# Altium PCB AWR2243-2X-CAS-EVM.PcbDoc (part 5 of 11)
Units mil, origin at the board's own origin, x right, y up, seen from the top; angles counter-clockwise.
Board outline 5118.11 x 3937.01 mil, 8 copper layers (Layer 1 - Top Layer, Layer 2 - GND, Layer 3 - Signal (Sensitive), Layer 4 - GND / Signal, Layer 5 - Signal, Layer 6 - PWR / Signal, Layer 7 - GND, Layer 8 - Bottom Layer), stack 54.8 mil thick; 629 components, 407 nets, 2243 pads, 3950 vias.
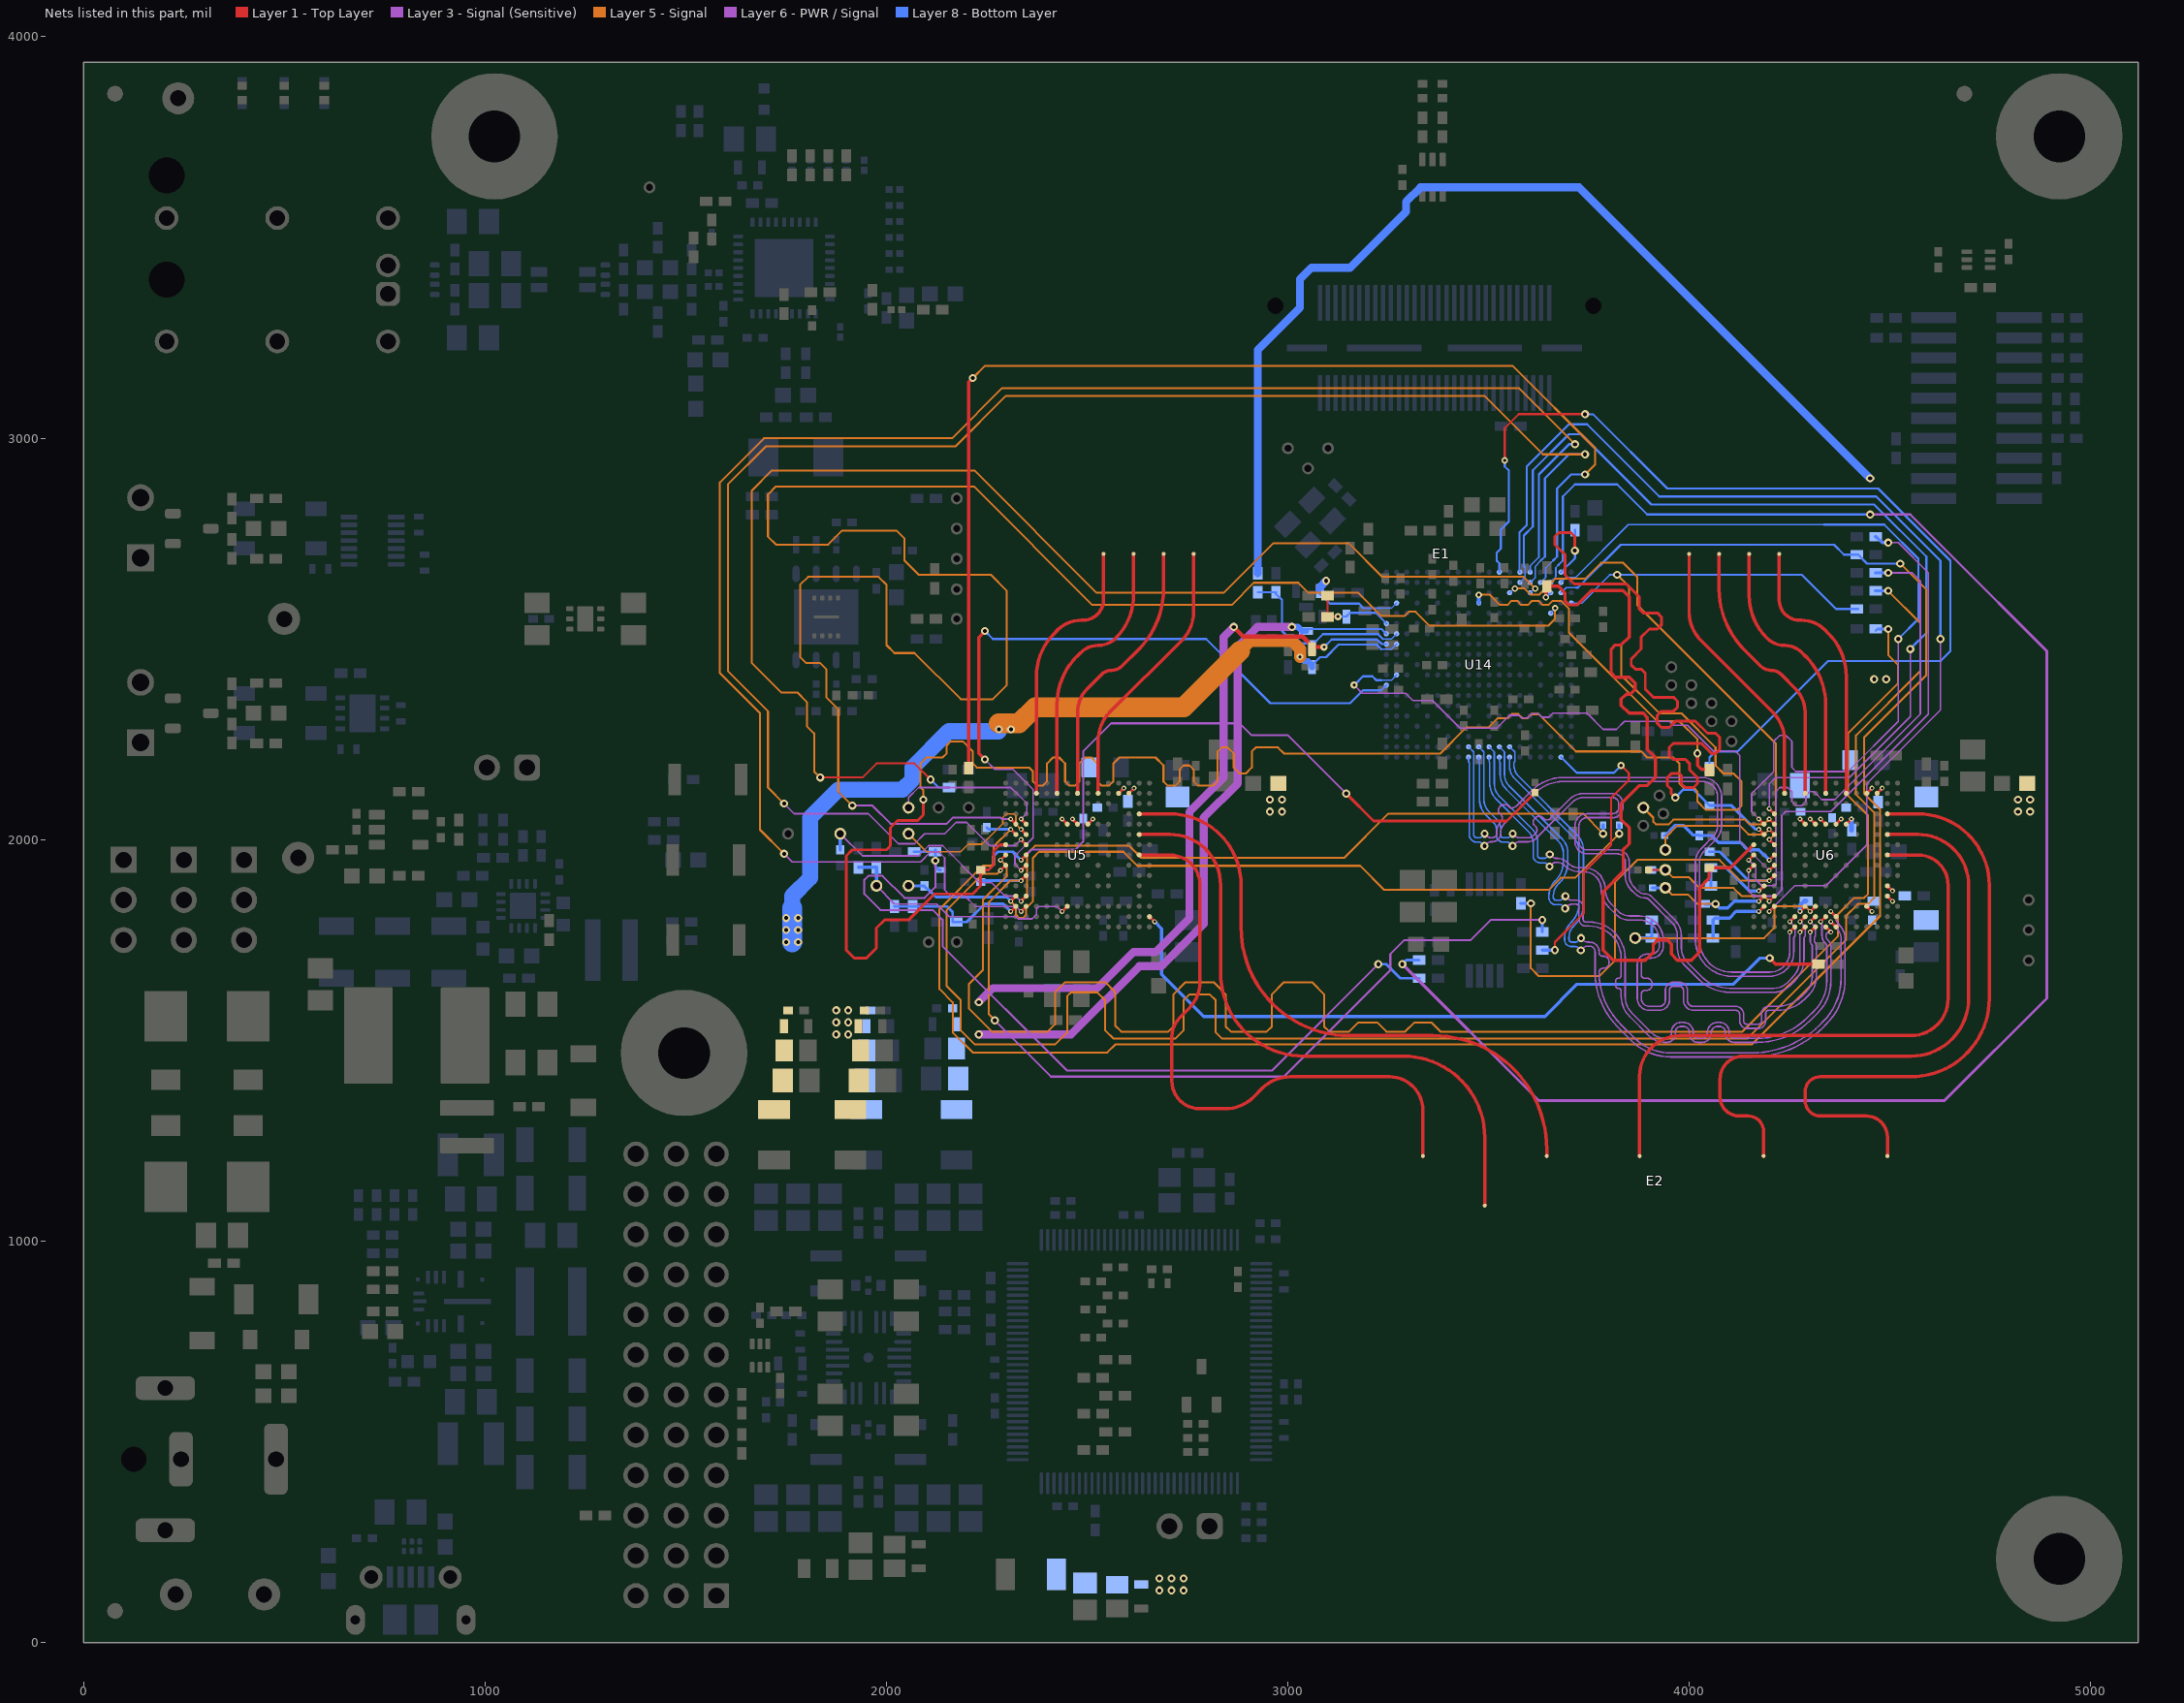
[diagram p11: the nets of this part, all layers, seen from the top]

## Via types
v1: diameter 13.78, hole 5.91, Layer 1 - Top Layer to Layer 2 - GND, tented top, 2104 vias
v2: diameter 20, hole 10, Layer 1 - Top Layer to Layer 8 - Bottom Layer, tented both sides, 831 vias
v3: diameter 7.87, hole 3.94, Layer 1 - Top Layer to Layer 2 - GND, tented top, 510 vias
v4: diameter 12, hole 6, Layer 1 - Top Layer to Layer 8 - Bottom Layer, tented both sides, 176 vias
v5: diameter 16, hole 8, Layer 1 - Top Layer to Layer 8 - Bottom Layer, tented both sides, 138 vias
v6: diameter 13.78, hole 5.91, Layer 1 - Top Layer to Layer 2 - GND, tented both sides, 88 vias
v7: diameter 18, hole 8, Layer 1 - Top Layer to Layer 8 - Bottom Layer, tented both sides, 41 vias
v8: diameter 22, hole 12, Layer 1 - Top Layer to Layer 8 - Bottom Layer, tented both sides, 36 vias
v9: diameter 19.68, hole 7.87, Layer 1 - Top Layer to Layer 8 - Bottom Layer, tented both sides, 26 vias

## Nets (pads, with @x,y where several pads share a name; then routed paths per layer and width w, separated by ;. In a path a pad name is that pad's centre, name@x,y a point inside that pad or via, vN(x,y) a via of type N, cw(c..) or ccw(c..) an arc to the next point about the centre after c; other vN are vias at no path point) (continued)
FE1_GPIO1: U5.N7 U14.V15 | length 4240.3
  Layer 1 - Top Layer w7: v4(2335.24,2000.39) U5.N7@2348.03,1987.6
  Layer 3 - Signal (Sensitive) w4: v2(1745,2090) 1770,2065 1955,2065 2030,1990 2070,1990 2095,2015 2145,2015 2173,2043 2200,2043 2258,1985 2319.84,1985 v4(2335.24,2000.39)
  Layer 5 - Signal w5: v2(1745,2090) 1705,2130 1705,2320 1605,2420 1605,2885 1700,2980 2171.72,2980 2296.72,3105 3490,3105 3635,2960 v2(3740,2960)
  Layer 8 - Bottom Layer w4: U14.V15@3603.86,2640.38 3616.14,2652.67 3616.14,2680.25 3629.44,2694.95
  Layer 8 - Bottom Layer w5.5: 3629.44,2694.95 3640,2705.52 3640,2900 3700,2960 v2(3740,2960)
FE1_GPIO2: U5.N13 U14.W15 | length 4384.6
  Layer 1 - Top Layer w7: v4(2335.24,1821.26) U5.N13@2348.03,1834.06
  Layer 3 - Signal (Sensitive) w4: v2(1745,1965) 1765,1945 2085,1945 2110,1970 2130,1970 2145,1955 2145,1875 2160,1860 2195,1860 2220.94,1834.06 2322.44,1834.06 v4(2335.24,1821.26)
  Layer 5 - Signal w5: v2(1745,1965) 1685,2025 1685,2315 1585,2415 1585,2890 1695,3000 2163.43,3000 2288.43,3125 3575,3125 v2(3715,2985)
  Layer 8 - Bottom Layer w4: U14.W15@3603.35,2666.46 3603.35,2682.3 3625,2703.95
  Layer 8 - Bottom Layer w5.5: 3625,2703.95 3625,2910 3700,2985 3711.36,2985 v2@3713.18,2986.82
FE1_I2C_SCL: R158.2 U14.U15 | length 3381.8
  Layer 1 - Top Layer w5: v2(1835,2155) 1940,2155 1975,2190 2070,2190 v2(2110,2150)
  Layer 5 - Signal w5: v2(1835,2155) 1820,2170 1820,2265 1802,2283 1802,2343 1778,2367 1738,2367 1665,2440 1665,2870 1715,2920 2218.79,2920 2523.79,2615 2774.87,2615 2840,2615 2963,2738 3152,2738 3235,2655 3587.07,2655 v5(3616.14,2625.93)
  Layer 8 - Bottom Layer w4: U14.U15@3603.35,2615.28 v5(3616.14,2625.93)
  Layer 8 - Bottom Layer w5: v2(2110,2150) 2130,2130 R158.2@2156.38,2130
FE1_I2C_SDA: R40.2 U14.V16 | length 3033.9
  Layer 1 - Top Layer w8: R40.2@2205,2178.62 2205,3140 v2(2215,3150)
  Layer 5 - Signal w5: v2(2215,3150) 2245,3180 3560,3180 3765,2975 3765,2935 v2(3740,2910)
  Layer 8 - Bottom Layer w4: U14.V16@3628.94,2640.87 3641.73,2653.66 3641.73,2676.73 3659.82,2694.82
  Layer 8 - Bottom Layer w5.5: 3659.82,2694.82 3670,2705 3670,2875 3705,2910 v2(3740,2910)
FE1_MCU_CLK_OUT: U5.N9 U14.H1 | length 1821.2
  Layer 1 - Top Layer w7: v4(2335.24,1923.62) U5.N9@2348.03,1936.42
  Layer 1 - Top Layer w8: v2(2245,2200) 2230,2215 2230,2503.89 2245,2518.89 v2(2245,2520)
  Layer 3 - Signal (Sensitive) w4: v2(2245,2200) 2270,2175 2315,2175 2365,2125 2365,2005 2320,1960 2320,1938.86 v4(2335.24,1923.62)
  Layer 8 - Bottom Layer w5.5: v2(2245,2520) 2265,2500 2796.36,2500 2956.36,2340 3155,2340 3187,2372 3232.12,2372 U14.H1@3245.08,2384.96
FE1_nERROR_OUT: R47.2 R181.1 U5.N8 | length 1841.6
  Layer 1 - Top Layer w7: v4(2335.24,1949.21) U5.N8@2348.03,1962.01 ; v2(3145,2115) 3213,2047 3544.99,2047 3609.44,2111.45 3610.23,2111.45 3615,2116.22 R47.2@3615,2117.01
  Layer 3 - Signal (Sensitive) w5: v4(2335.24,1949.21) 2361.02,1975 2470,1975 2490,1995 2490,2220 2560,2290 2880,2290 2910,2260 3000,2260 v2(3145,2115)
  Layer 8 - Bottom Layer w7: R181.1@2234.68,1925 2255,1925 2267,1937 2267,1959 2278,1970 2314.45,1970 v4(2335.24,1949.21)
FE1_nRESET: R161.2 R179.2 TP32.1 U5.P12 | length 2096.1
  Layer 1 - Top Layer w7: v4(2309.65,1846.85) U5.P12@2322.44,1859.65
  Layer 5 - Signal w5: v4(2309.65,1846.85) 2322.44,1834.06 2322.44,1812.56 2330,1805 2340,1805 2348.03,1813.03 2348.03,1830 2365,1846.97 2365,1955 2380,1970 2590,1970 2625,1935 3180,1935 3240,1875 3650,1875 3680,1905 3715,1905 v2(3825,2015)
  Layer 8 - Bottom Layer w7: TP32.1@2055,1885.2 2094.88,1885.2 R179.2@2095,1885.31 2095,1883.35 2101.34,1877 2103.31,1877 2123.31,1857 2299.5,1857 v4(2309.65,1846.85)
  Layer 8 - Bottom Layer w8: v2(3825,2015) R161.2@3825,2037.01
FE1_nWARM_RESET: R162.2 R175.1 TP26.1 U5.N12 | length 2267.7
  Layer 1 - Top Layer w7: v4(2335.24,1846.85) U5.N12@2348.03,1859.65
  Layer 3 - Signal (Sensitive) w4: TP26.1@1885,2015 1940,1960 2080,1960 2105,1985 2140,1985 2232,1893 2262,1893 2295.35,1859.65 2322.44,1859.65 v4(2335.24,1846.85)
  Layer 5 - Signal w5: v4(2335.24,1846.85) 2350,1861.61 2350,1965 2370,1985 2605,1985 2635,1955 3140,1955 3250,2065 3735,2065 v2(3785,2015)
  Layer 8 - Bottom Layer w8: R175.1@1884.68,1975 R175.1@1885,1974.68 TP26.1@1885,2015 ; v2(3785,2015) R162.2@3785,2037.01
FE1_OSC_CLKOUT: C61.2 U5.A14 | length 1902
  Layer 1 - Top Layer w7: U5.A14@2655.12,1808.46 v4(2667.91,1795.67)
  Layer 1 - Top Layer w8.4: v2(4200,1705) 4215,1690 C61.2@4321.38,1690
  Layer 8 - Bottom Layer w8: v4(2667.91,1795.67) 2685,1778.58 2685,1665 2790,1560 3640,1560 3720,1640 4110,1640 4175,1705 v2(4200,1705)
FE1_RS232_RX: TP20.1 U5.N5 | length 409.6
  Layer 1 - Top Layer w7: v4(2335.24,2051.57) U5.N5@2348.03,2038.78
  Layer 3 - Signal (Sensitive) w4: TP20.1@2055,2080 2055,2105 2080,2130 2310,2130 2350,2090 2350,2066.34 v4(2335.24,2051.57)
FE1_RS232_TX: TP27.1 U5.N6 | length 393.8
  Layer 1 - Top Layer w7: v4(2335.24,2025.98) U5.N6@2348.03,2013.19
  Layer 5 - Signal w4: TP27.1@2055,2015 2100,1970 2185,1970 2203.86,1988.86 2238.86,1988.86 2290,2040 2290,2055 2299.05,2064.05 2299.05,2064.37 2318.74,2064.37 2322.44,2060.67 2322.44,2038.78 v4(2335.24,2025.98)
FE1_RX1: "E1.D1 - RX1" U5.M2 | length 686.3
  Layer 1 - Top Layer w8.4: U5.M2@2373.62,2115.55 2373.62,2407.24 cw(c2524.28,2407.24) 2417.75,2513.77 2426.24,2522.26 cw(c2485.98,2462.51) 2485.98,2547.01 2489.77,2547.01 ccw(c2489.77,2598.22) 2525.98,2562.01 ccw(c2490.82,2597.18) 2540.55,2597.18 2540.55,2712.01
FE1_RX2: "E1.D1 - RX2" U5.K2 | length 686.3
  Layer 1 - Top Layer w8.4: U5.K2@2424.8,2115.55 2424.8,2337.17 cw(c2592.97,2337.17) 2474.06,2456.08 2484.31,2466.33 cw(c2526.98,2423.65) 2526.98,2484.01 ccw(c2526.98,2546.78) 2571.34,2502.36 ; 2571.34,2502.36 ccw(c2465.08,2608.62) 2615.35,2608.62 2615.35,2712.01
FE1_RX3: "E1.D1 - RX3" U5.H2 | length 686.8
  Layer 1 - Top Layer w8.4: U5.H2@2475.98,2115.55 2475.98,2316.65 cw(c2561.34,2316.65) 2476,2318.45 cw(c2561.34,2316.65) 2500.98,2377.01 2535.38,2411.4 cw(c2560.98,2385.79) 2560.98,2422.01 ccw(c2560.98,2458.22) 2586.59,2432.61 2627.75,2473.78 ccw(c2477.1,2624.43) 2690.16,2624.43 2690.16,2712.01
FE1_RX4: "E1.D1 - RX4" U5.F2 | length 686.3
  Layer 1 - Top Layer w8.4: U5.F2@2527.17,2115.55 2527.17,2246.77 cw(c2627.17,2246.77) 2556.45,2317.48 2735.67,2496.7 ccw(c2664.96,2567.41) 2764.96,2567.41 2764.96,2712.01
FE1_SCALED: C126.1 R26.1 R28.2 U14.P1 | length 214.6
  Layer 1 - Top Layer w5.5: R26.1@3098.62,2608 R28.2@3098.62,2555 3099.59,2555.97 v7(3125,2555.97)
  Layer 8 - Bottom Layer w5.5: v7(3125,2555.97) C126.1@3145.69,2555.97 3154.72,2565 3218.58,2565 U14.P1@3245.08,2538.5
FE1_SOP0: R171.2 R172.1 TP31.1 U5.J13 | length 632.3
  Layer 1 - Top Layer w7: v4(2437.6,1821.26) U5.J13@2450.39,1834.06
  Layer 3 - Signal (Sensitive) w4: TP31.1@1975,1885.2 2020.2,1840 2125,1840 2156.54,1808.46 2322.44,1808.46 2327.9,1803 2363,1803 2373.62,1813.62 2373.62,1827.62 2380.06,1834.06 2424.8,1834.06 v4(2437.6,1821.26)
  Layer 8 - Bottom Layer w8: R172.1@1930,1931.38 R171.2@1975,1931.38 TP31.1@1975,1885.2
FE1_SOP1_SYNC_OUT: R173.1 R174.2 R183.1 R203.2 | length 2153.5
  Layer 3 - Signal (Sensitive) w5: v2(2121.69,1948) 2121.69,1881.69 2095,1855 2045,1855 1990,1910 1955,1910 1945,1900 1945,1865 1985,1825 2115,1825 2140,1800 2140,1735 2450,1425 2960,1425 v2(3225,1690)
  Layer 8 - Bottom Layer w7: R174.2@2068.62,1970 R173.1@2121.38,1970 R173.1@2121.69,1970 ; R173.1@2121.69,1975 R173.1@2121.69,1970 ; R183.1@2135,1925 2130,1925 2121.69,1933.31 v2(2121.69,1948) R173.1@2121.69,1970 ; v2(3225,1690) 3245,1690 3280,1655 R203.2@3326.38,1655
FE1_SOP2: R188.2 R189.1 R193.1 U5.P13 | length 364.8
  Layer 1 - Top Layer w7: v4(2309.65,1821.26) U5.P13@2322.44,1834.06
  Layer 8 - Bottom Layer w7: R189.1@2020,1833.62 R188.2@2065,1833.62 2151.38,1833.62 2165,1820 2165,1795 R193.1@2173.62,1795 2200,1795 2245,1840 2290.9,1840 v4(2309.65,1821.26)
FE1_SPI_CLK: R140.1 U5.R9 | length 4271.6
  Layer 1 - Top Layer w7: v4(2284.05,1923.62) U5.R9@2296.85,1936.42
  Layer 5 - Signal w5: v4(2284.05,1923.62) 2275.43,1915 2240,1915 2150,1825 2150,1635 2185,1600 2185,1525 2220,1490 2420,1490 2450,1520 2450,1610 2460,1620 2525,1620 2545,1600 2545,1525 2565,1505 2720,1505 2740,1525 2740,1600 2755,1615 2805,1615 2820,1600 2820,1520 2835,1505 3110,1505 4043.05,1505 4145,1505 4390,1750 4390,1810 4420,1840 4445,1840 4460,1855 4460,2068 4415,2113 4415,2260 4575,2420 4575,2540 v2(4495,2620)
  Layer 8 - Bottom Layer w8: R140.1@4463.62,2620 v2(4495,2620)
FE1_SPI_CS0: R56.1 R141.1 U5.R7 U14.T19 | length 5713.8
  Layer 1 - Top Layer w7: v2(2092,2100) 2092,2062 2078,2048 2028,2048 2010,2030 2010,1985 2000,1975 1915,1975 1900,1960 1900,1725 1920,1705 1950,1705 1975,1730 1975,1780 1995,1800 2055,1800 2120,1865 2215,1865 2234.68,1884.68 R56.1@2234.68,1925 2255,1925 2267,1937 2267,1972 2282.6,1987.6 U5.R7@2296.85,1987.6
  Layer 5 - Signal w5: v2(2092,2100) 2092,2123 2085,2130 2085,2190 2100,2205 2140,2205 2150,2215 2150,2235 2160,2245 2190,2245 2215,2220 2215,2190 2225,2180 2355,2180 2365,2170 2365,2145 2375,2135 2390,2135 2400,2145 2400,2190 2415,2205 2430,2205 2445,2190 2445,2145 2455,2135 2470,2135 2480,2145 2480,2190 2495,2205 2510,2205 2525,2190 2525,2145 2535,2135 2555,2135 2565,2145 2565,2190 2580,2205 2670,2205 2690,2185 2690,2145 2700,2135 2720,2135 2730,2145 2730,2175 2740,2185 2755,2185 2765,2175 2765,2145 2775,2135 2815,2135 2825,2145 2825,2220 2835,2230 2850,2230 2865,2215 2865,2180 2880,2165 2895,2165 2910,2180 2910,2220 2920,2230 2975,2230 2990,2215 3380,2215 3445,2280 3500,2280 3523,2303 3548,2303 3558,2313 3574,2313 3584,2303 3597,2303 3607,2313 3624,2313 3717,2220 3880,2220 3895,2205 3960,2205 3975,2190 3975,2140 3985,2130 4010,2130 4020,2120 4020,2095 4040,2075 4120,2075 4130,2085 4130,2145 4110,2165 4085,2165 4065,2185 4065,2230 3980,2315 3925,2315 3830,2410 3830,2485 3850,2505 3850,2630 v2(3820,2660)
  Layer 8 - Bottom Layer w4: U14.T19@3705.71,2589.69 3731.69,2589.69 3802,2660
  Layer 8 - Bottom Layer w5.5: 3802,2660 v2(3820,2660) 4280,2660 4365,2575 R141.1@4416.38,2575 R141.1@4420.32,2575
FE1_SPI_IRQ: R136.2 R160.2 U5.P6 U14.U18 | length 5055.7
  Layer 1 - Top Layer w7: v4(2309.64,2025.98) U5.P6@2322.44,2013.19
  Layer 5 - Signal w5: v4(2309.64,2025.98) 2267,1983.34 2267,1942 2260,1935 2240,1935 2132,1827 2132,1628 2165,1595 2165,1520 2215,1470 2550,1470 2570,1490 4048.05,1490 4155,1490 4475,1810 4475,2075 4435,2115 4435,2255 4590,2410 4590,2623 v2(4525,2688)
  Layer 8 - Bottom Layer w4: U14.U18@3680.12,2615.28 3692.91,2628.07 3718.09,2628.07
  Layer 8 - Bottom Layer w5.5: 3718.09,2628.07 3722.07,2628.07 3829,2735 4360,2735 4385,2710 R136.2@4416.38,2710 4420.32,2710 4442.32,2688 v2(4525,2688)
  Layer 8 - Bottom Layer w7: R160.2@2250,2030.31 2254.33,2025.98 v4(2309.64,2025.98)
FE1_SPI_MISO: U5.P5 U14.R17 | length 5084.7
  Layer 1 - Top Layer w7: v4(2309.64,2051.57) U5.P5@2322.44,2038.78
  Layer 3 - Signal (Sensitive) w5: v2(1915,2085) 1965,2085 2010,2040 2150,2040 2165,2055 2285,2055 2288.43,2051.57 v4(2309.64,2051.57)
  Layer 5 - Signal w5: v2(1915,2085) 1880,2120 1880,2325 1850,2355 1850,2425 1835,2440 1800,2440 1785,2455 1785,2635 1805,2655 1980,2655 2000,2635 2000,2485 2020,2465 2070,2465 2185,2350 2265,2350 2300,2385 2300,2620 2260,2660 2080,2660 2045,2695 2045,2750 2025,2770 1890,2770 1855,2735 1725,2735 1705,2755 1705,2860 1725,2880 2217.57,2880 2512.57,2585 2860,2585 2915,2640 3025.64,2640 3050.64,2615 3175,2615 3232.8,2557.2 3290.2,2557.2 3301,2568 3318,2568 3353,2533 3648,2533 3665.18,2550.18 v5(3665.18,2576.89)
  Layer 8 - Bottom Layer w4: U14.R17@3654.53,2564.09 v5(3665.18,2576.89)
FE1_SPI_MOSI: R145.1 U5.R8 | length 4274.9
  Layer 1 - Top Layer w7: v4(2284.05,1949.21) U5.R8@2296.85,1962.01
  Layer 5 - Signal w5: v4(2284.05,1949.21) 2300,1933.27 2300,1910 2240,1850 2240,1675 2205,1640 2205,1580 2263.05,1521.95 2401.95,1521.95 2420,1540 2420,1620 2445,1645 2545,1645 2570,1620 2570,1536.95 2585,1521.95 2701.95,1521.95 2715,1535 2715,1615 2745,1645 2815,1645 2845,1615 2845,1535 2858.05,1521.95 2946.95,1521.95 2960,1535 2960,1615 2990,1645 3060,1645 3090,1615 3090,1535 3103.05,1521.95 3151.95,1521.95 3175,1545 3221.95,1545 3245,1521.95 3291.95,1521.95 3315,1545 3356.95,1545 3380,1521.95 3920,1521.95 4131.95,1521.95 4370,1760 4370,1815 4410,1855 4435,1855 4445,1865 4445,2060 4395,2110 4395,2265 4520,2390 4520,2435 4495,2460 v2(4495,2525)
  Layer 8 - Bottom Layer w5: R145.1@4463.62,2520 R145.1@4468.62,2525
  Layer 8 - Bottom Layer w8: R145.1@4468.62,2525 v2(4495,2525)
FE1_SYNC_FROM_SOC: R201.2 U14.V17 | length 4378.1
  Layer 3 - Signal (Sensitive) w5.5: v2(4450,2810) 4550,2810 4770,2590
  Layer 3 - Signal (Sensitive) w7: v2(3285,1690) 3625,1350 4635,1350 4890,1605 4890,2470 4770,2590
  Layer 8 - Bottom Layer w4: U14.V17@3654.53,2640.87 3654.53,2642.57 3667.32,2655.37 3667.32,2677.91 3673.93,2684.52
  Layer 8 - Bottom Layer w5.5: 3673.93,2684.52 3685,2695.59 3685,2855 3715,2885 3820,2885 3895,2810 v2(4450,2810)
  Layer 8 - Bottom Layer w7: v2(3285,1690) 3295,1700 R201.2@3326.38,1700
FE1_SYNC_IN: R185.2 R195.1 U5.N10 | length 2164.9
  Layer 1 - Top Layer w7: v4(2335.24,1898.03) U5.N10@2348.03,1910.83
  Layer 3 - Signal (Sensitive) w5: v2(2270,1550) 2410,1410 2990,1410 3255,1675 3255,1715 3290,1750 3455,1750 3505,1800 v2(3633.62,1800)
  Layer 5 - Signal w5: v2(2270,1550) 2255,1565 2255,1845 2308.03,1898.03 v4(2335.24,1898.03)
  Layer 8 - Bottom Layer w7: R185.2@2234.69,1890 R185.2@2234.68,1895 2237.72,1898.03 v4(2335.24,1898.03) ; R195.1@3633.62,1770 v2(3633.62,1800)
FE1_TX1: "E2.D1 - TX1" U5.B4 | length 1554.4
  Layer 1 - Top Layer w8.4: U5.B4@2629.53,2064.37 2705.98,2064.37 cw(c2705.98,1887.01) 2883.35,1887.01 2883.35,1781.12 ccw(c3152.46,1781.12) 3152.46,1512.01 3361.81,1512.01 cw(c3361.81,1229.26) 3644.57,1229.26 3644.57,1212.01
FE1_TX2: "E2.D1 - TX2" U5.B6 | length 1554.8
  Layer 1 - Top Layer w8.4: U5.B6@2629.53,2013.19 2705.98,2013.19 cw(c2705.98,1887.01) 2832.17,1887.01 2832.17,1669.11 ccw(c3040.44,1669.11) 3040.44,1460.83 3287.42,1460.83 cw(c3287.42,1257.93) 3490.31,1257.93 3490.32,1088.58
FE1_TX3: "E2.D1 - TX3" U5.B8 | length 1554.8
  Layer 1 - Top Layer w8.4: U5.B8@2629.53,1962.01 2705.98,1962.01 cw(c2705.98,1887.01) 2780.98,1887.01 2780.98,1647.01 cw(c2684.42,1647.01) 2752.7,1578.72 2730.98,1557.01 ccw(c2779.27,1508.72) 2710.98,1508.72 2710.98,1399.02 ccw(c2780,1399.02) 2780,1330 2843.58,1330 ccw(c2843.58,1430) 2914.29,1359.29 2935.36,1380.36 cw(c3006.07,1309.65) 3006.07,1409.65 3252.58,1409.65 cw(c3252.58,1326.2) 3336.02,1326.2 3336.02,1212.01
FE1_VRF1_FILTERED: C64.1 C67.1 C69.1 C73.1 C128.1 C132.1 C141.1 C147.1 L5.2 U5.G5 U5.H5 U5.J5 U14.M2 | length 2112.9
  Layer 1 - Top Layer w7: v4(2437.6,2051.57) U5.J5@2450.39,2038.78 ; v4(2463.19,2051.57) U5.H5@2475.98,2038.78 ; U5.G5@2501.57,2038.78 v4(2514.37,2051.58)
  Layer 5 - Signal w30: 2880,2470 2905,2495 3010,2495 3030,2475 v5(3030,2455)
  Layer 5 - Signal w50: 2280,2290 2330,2290 2370,2330 2740,2330 2880,2470
  Layer 8 - Bottom Layer w4: 3232.37,2474.53 3257.87,2474.53 U14.M2@3270.67,2487.32
  Layer 8 - Bottom Layer w5.5: C128.1@3060,2435 3080,2455 3095,2455 3126,2486 3220.89,2486 3232.37,2474.53
  Layer 8 - Bottom Layer w15: v5(3030,2455) 3040,2445 3050,2445 C128.1@3060,2435 ; C128.1@3060,2435 C128.1@3060,2430 C128.1@3060,2435
  Layer 8 - Bottom Layer w40: 1765,1830 1765,1860 1810,1905 1810,2055 1880,2125 2040,2125 2065,2150 2065,2180 2155,2270 v2@2280,2270
  Layer 8 - Bottom Layer w50: 1765,1745 1765,1830
  other v2: 1750,1745 1780,1745 1750,1775 1780,1775 1750,1805 1780,1805 2280,2275 2310,2275
FE1_VRF2_FILTERED: C65.1 C68.1 C70.1 C74.1 C123.1 C134.1 C138.1 L6.2 R44.2 U5.C2 U5.D2 U14.T2 | length 285.6
  Layer 1 - Top Layer w7: U5.D2@2578.35,2115.55 v4(2591.14,2128.35) ; U5.C2@2603.94,2115.55 v4(2616.73,2128.35)
  Layer 8 - Bottom Layer w4: 3228.29,2576.89 3257.87,2576.89 U14.T2@3270.67,2589.69
  Layer 8 - Bottom Layer w5.5: C123.1@3080,2620 3080,2612.5 3104.5,2588 3177,2588 3188.11,2576.89 3228.29,2576.89
  Layer 8 - Bottom Layer w20: C123.1@3080,2620 3080,2630 v2(3095,2645)
  other v2: 1875,1515 1905,1515 1875,1545 1905,1545 1875,1575 1905,1575 2955,2070 2985,2070 2955,2100 2985,2100
FE2_1V8_FILTERED: C135.1 C142.1 C148.1 C160.1 C163.1 C166.1 C168.1 C171.1 C239.1 C240.1 C241.1 L23.2 R138.2 U6.B11 U6.B12 U6.D13 U6.F5 U6.K5 U6.K13 | length 2776.7
  Layer 1 - Top Layer w7: v4(4275.39,1821.26) U6.K13@4288.19,1834.06 ; v4(4275.39,2051.57) U6.K5@4288.19,2038.78 ; U6.F5@4390.55,2038.78 v4(4403.35,2051.58) ; U6.D13@4441.73,1834.06 v4(4454.53,1821.26) ; U6.B12@4492.91,1859.65 v4(4505.71,1846.85) ; U6.B11@4492.91,1885.24 v4(4505.71,1872.44)
  Layer 8 - Bottom Layer w12: v4(4275.39,1821.26) 4275.39,1835.59 4286.81,1847.01 C163.1@4290.75,1847.01 ; C148.1@4403.35,2023.66 v4(4403.35,2051.58)
  Layer 8 - Bottom Layer w20: R138.2@2925,2663.62 2925,3220 3030,3325 3030,3396.25 3058.75,3425 3155,3425 3294.08,3564.08 3294.08,3589.08 3330,3625 3725,3625 v2(4450,2900)
  other v2: 2680,130 2710,130 2740,130 2680,160 2710,160 2740,160 4460,2400 4490,2400
FE2_CSI2_CLK_N: U6.J14 U14.A11 | length 1726.1
  Layer 1 - Top Layer w7: v4(4300.98,1795.67) U6.J14@4313.78,1808.46
  Layer 3 - Signal (Sensitive) w4: v2(3651.5,1933.16) 3657.76,1939.42 cw(c3668,1929.18) 3668,1943.66 3671,1943.66 cw(c3671,1918.7) 3688.64,1936.36 3690,1935 ccw(c3726.21,1971.21) 3726.21,1920 3737.68,1920 cw(c3737.68,1877.68) 3780,1877.68 ccw(c3844.75,1877.68) 3798.97,1831.89 3817.32,1813.54 ccw(c3850,1846.21) 3850,1800 3875,1800 cw(c3875,1750) 3925,1750 3925,1735.49 cw(c3904.51,1735.49) 3904.51,1715 3895,1715 ccw(c3895,1690) 3870,1690 3870,1605 ccw(c3900,1605) 3900,1575 3925,1575 ccw(c3925,1600) 3950,1600 3950,1625 cw(c3960,1625) 3960,1635 3975,1635 cw(c3975,1625) 3985,1625 3985,1600 ccw(c4010,1600) 4010,1575 4115,1575 cw(c4115,1565) 4125,1565 4125,1549.14 ccw(c4144.14,1549.14) 4144.14,1530 4170.86,1530 ccw(c4170.86,1549.14) 4190,1549.14 4190,1567.93 cw(c4197.07,1567.93) 4197.07,1575 4219.64,1575 ccw(c4219.64,1670.36) 4287.07,1602.93 4297.07,1612.93 ccw(c4251.37,1658.63) 4316,1658.63 4316,1735.34 ccw(c4302.34,1735.34) 4312,1745 cw(c4314.45,1747.45) 4310.98,1747.45 4310.98,1754.58 cw(c4315.82,1754.58) 4312.4,1758 ccw(c4309.07,1761.33) 4313.78,1761.33 4313.78,1777 ccw(c4299.6,1777) 4309.63,1787.03 v4(4300.98,1795.67)
  Layer 8 - Bottom Layer w4: U14.A11@3500.98,2205.83 3500.98,2193.85 3502.78,2192.06 3502.78,2140 ccw(c3559.12,2140) 3519.28,2100.16 3599.72,2019.72 cw(c3572.49,1992.49) 3611,1992.49 3611,1959.66 ccw(c3628,1959.66) 3628,1942.66 3638,1942.66 cw(c3638,1933.01) 3644.82,1939.84 v2(3651.5,1933.16)
FE2_CSI2_CLK_P: U6.J15 U14.B11 | length 1726.1
  Layer 1 - Top Layer w7: v4(4300.98,1770.08) U6.J15@4313.78,1782.87
  Layer 3 - Signal (Sensitive) w4: v2(3652,1963.66) 3657.77,1957.9 ccw(c3668,1968.15) 3668,1953.66 3671,1953.66 cw(c3671,1918.7) 3695.72,1943.42 3697.07,1942.07 ccw(c3726.21,1971.21) 3726.21,1930 3737.68,1930 cw(c3737.68,1877.68) 3790,1877.68 ccw(c3844.75,1877.68) 3806.03,1838.97 3824.39,1820.61 ccw(c3850,1846.21) 3850,1810 3875,1810 cw(c3875,1750) 3935,1750 3935,1735.48 cw(c3904.52,1735.48) 3904.52,1705 3895,1705 ccw(c3895,1690) 3880,1690 3880,1663.46 ccw(c3888.46,1663.46) 3888.46,1655 3893.34,1655 cw(c3893.34,1641.34) 3907,1641.34 3907,1638.66 cw(c3893.34,1638.66) 3893.34,1625 3890.24,1625 ccw(c3890.24,1614.76) 3880,1614.76 3880,1605 ccw(c3900,1605) 3900,1585 3925,1585 ccw(c3925,1600) 3940,1600 3940,1625 cw(c3960,1625) 3960,1645 3975,1645 cw(c3975,1625) 3995,1625 3995,1600 ccw(c4010,1600) 4010,1585 4115,1585 cw(c4115,1565) 4135,1565 4135,1549.14 ccw(c4144.14,1549.14) 4144.14,1540 4170.86,1540 ccw(c4170.86,1549.14) 4180,1549.14 4180,1567.93 cw(c4197.07,1567.93) 4197.07,1585 4219.64,1585 ccw(c4219.64,1670.36) 4280,1610 4290,1620 ccw(c4251.37,1658.63) 4306,1658.63 4306,1735.34 ccw(c4302.34,1735.34) 4304.93,1737.93 cw(c4314.45,1747.45) 4300.98,1747.45 v4(4300.98,1770.08)
  Layer 8 - Bottom Layer w4: U14.B11@3500.98,2231.42 3513.78,2218.62 3513.78,2140 ccw(c3559.12,2140) 3527.06,2107.94 3607.5,2027.5 cw(c3572.49,1992.49) 3622,1992.49 3622,1960.49 ccw(c3628.83,1960.49) 3628.83,1953.66 3638,1953.66 ccw(c3638,1963.32) 3644.82,1956.49 v2(3652,1963.66)
FE2_CSI2_TX0_N: U6.G14 U14.A13 | length 1725.8
  Layer 1 - Top Layer w7: v4(4352.17,1821.26) U6.G14@4364.96,1808.46
  Layer 3 - Signal (Sensitive) w4: v2(3729.5,1724.5) 3735.76,1730.76 cw(c3746,1720.52) 3746,1735 3751.34,1735 cw(c3751.34,1721.34) 3765,1721.34 3765,1669.76 ccw(c3957.55,1669.76) 3821.4,1533.6 3855.6,1499.4 ccw(c3953.14,1596.94) 3953.14,1459 4155.02,1459 ccw(c4155.02,1710.38) 4332.77,1532.63 4340.45,1540.3 ccw(c4226.23,1654.52) 4387.76,1654.52 4387.76,1749.81 ccw(c4328.82,1749.81) 4370.49,1791.48 4368.9,1793.08 cw(c4378.42,1802.59) 4364.96,1802.59 ccw(c4350.78,1802.59) 4360.81,1812.62 v4(4352.17,1821.26)
  Layer 8 - Bottom Layer w4: U14.A13@3552.17,2205.83 3552.17,2182.23 ccw(c3594.48,2182.23) 3564.56,2152.31 3712.37,2004.5 cw(c3681.87,1974) 3725,1974 3725,1840.11 cw(c3660.89,1840.11) 3706.22,1794.78 3704.56,1793.11 ccw(c3742.11,1755.56) 3689,1755.56 3689,1751 ccw(c3706,1751) 3706,1734 3716,1734 cw(c3716,1724.34) 3722.83,1731.17 v2(3729.5,1724.5)
FE2_CSI2_TX0_P: U6.G15 U14.B13 | length 1726.1
  Layer 1 - Top Layer w7: v4(4352.17,1795.67) U6.G15@4364.96,1782.87
  Layer 3 - Signal (Sensitive) w4: v2(3730,1755) 3735.77,1749.23 ccw(c3746,1759.49) 3746,1745 3751.34,1745 cw(c3751.34,1721.34) 3775,1721.34 3775,1718.46 ccw(c3783.46,1718.46) 3783.46,1710 3786.34,1710 cw(c3786.34,1696.34) 3800,1696.34 3800,1693.48 cw(c3786.52,1693.48) 3786.52,1680 3785.24,1680 ccw(c3785.24,1669.76) 3775,1669.76 ccw(c3957.55,1669.76) 3828.47,1540.67 3862.67,1506.47 ccw(c3953.14,1596.94) 3953.14,1469 4155.02,1469 ccw(c4155.02,1710.38) 4325.7,1539.7 4333.38,1547.38 ccw(c4226.23,1654.52) 4377.76,1654.52 4377.76,1749.81 ccw(c4328.82,1749.81) 4363.42,1784.41 v4(4352.17,1795.67)
  Layer 8 - Bottom Layer w4: U14.B13@3552.17,2231.42 3564.96,2218.62 3564.96,2194.74 3563.17,2192.94 3563.17,2183.84 ccw(c3598.38,2183.84) 3573.48,2158.94 3720.15,2012.28 cw(c3681.87,1974) 3736,1974 3736,1840.11 cw(c3660.89,1840.11) 3714,1787 3712.33,1785.34 ccw(c3742.11,1755.56) 3700,1755.56 3700,1751.83 ccw(c3706.83,1751.83) 3706.83,1745 3716,1745 ccw(c3716,1754.66) 3722.83,1747.82 v2(3730,1755)
FE2_CSI2_TX1_N: U6.H14 U14.B12 | length 1725.8
  Layer 1 - Top Layer w7: v4(4326.57,1795.67) U6.H14@4339.37,1808.46
  Layer 3 - Signal (Sensitive) w4: v2(3691,1859.33) 3696.77,1853.57 ccw(c3707,1863.82) 3707,1849.33 3717.84,1849.33 cw(c3717.84,1832.17) 3735,1832.17 3735,1802.07 ccw(c3742.07,1802.07) 3742.07,1795 3750,1795 cw(c3750,1705) 3840,1705 3840,1610 ccw(c3900.36,1610) 3857.68,1567.32 3905.86,1519.14 ccw(c3940,1553.28) 3940,1505 3943.1,1505 ccw(c3943.1,1516.9) 3955,1516.9 3955,1521.1 cw(c3978.9,1521.1) 3978.9,1545 3984.68,1545 cw(c3984.68,1519.68) 4010,1519.68 4010,1516.9 ccw(c4021.9,1516.9) 4021.9,1505 4030.24,1505 ccw(c4030.24,1518.9) 4044.14,1518.9 cw(c4070.24,1518.9) 4070.24,1545 4075.24,1545 cw(c4075.24,1521.1) 4099.14,1521.1 4099.14,1518.41 ccw(c4112.56,1518.41) 4112.56,1505 4168.49,1505 ccw(c4168.49,1682.46) 4293.98,1556.98 4311.5,1574.5 ccw(c4237.45,1648.54) 4342.17,1648.54 4342.17,1734 ccw(c4330.49,1734) 4338.76,1742.24 4337,1744 cw(c4353.9,1760.9) 4330,1760.9 4330,1787.4 ccw(c4318.31,1787.4) v4@4326.73,1795.51 ; v4@4326.73,1795.51 ccw(c4318.31,1787.4) v4(4326.57,1795.67) v4@4326.73,1795.51
  Layer 8 - Bottom Layer w4: U14.B12@3526.57,2231.42 3539.37,2218.62 3539.37,2163.36 ccw(c3582.18,2163.36) 3551.91,2133.09 3682.17,2002.83 cw(c3646.3,1967) 3697,1967 3697,1944.44 cw(c3621.89,1944.44) 3675,1891.33 3673.33,1889.67 ccw(c3703.11,1859.89) 3661,1859.89 3661,1856.16 ccw(c3667.83,1856.16) 3667.83,1849.33 3677,1849.33 ccw(c3677,1858.99) 3683.82,1852.16 v2(3691,1859.33)
FE2_CSI2_TX1_P: U6.H15 U14.A12 | length 1726.5
  Layer 1 - Top Layer w7: U6.H15@4339.37,1782.87 v4(4352.17,1770.08)
  Layer 3 - Signal (Sensitive) w4: v2(3690.5,1828.83) 3696.76,1835.09 cw(c3707,1824.85) 3707,1839.33 3717.84,1839.33 cw(c3717.84,1832.17) 3725,1832.17 3725,1802.07 ccw(c3742.07,1802.07) 3742.07,1785 3750,1785 cw(c3750,1705) 3830,1705 3830,1662 cw(c3823,1662) 3823,1655 ccw(c3823,1648) 3816,1648 3816,1637 ccw(c3823,1637) 3823,1630 cw(c3823,1623) 3830,1623 3830,1610 ccw(c3900.36,1610) 3850.61,1560.25 3898.79,1512.07 ccw(c3940,1553.28) 3940,1495 3943.1,1495 ccw(c3943.1,1516.9) 3965,1516.9 3965,1521.1 cw(c3978.9,1521.1) 3978.9,1535 3984.68,1535 cw(c3984.68,1519.68) 4000,1519.68 4000,1516.9 ccw(c4021.9,1516.9) 4021.9,1495 4027.5,1495 4030.24,1495 ccw(c4030.24,1518.9) 4054.14,1518.9 cw(c4070.24,1518.9) 4070.24,1535 4075.24,1535 cw(c4075.24,1521.1) 4089.14,1521.1 4089.14,1518.41 ccw(c4112.56,1518.41) 4112.56,1495 4168.49,1495 ccw(c4168.49,1682.46) 4301.05,1549.91 4318.57,1567.43 ccw(c4237.45,1648.54) 4352.17,1648.54 4352.17,1734 ccw(c4330.49,1734) 4345.82,1749.32 4344.07,1751.07 cw(c4353.9,1760.9) 4340,1760.9 cw(c4349.18,1760.9) 4349.18,1770.08 v4(4352.17,1770.08)
  Layer 8 - Bottom Layer w4: U14.A12@3526.57,2205.83 3526.57,2193.85 3528.37,2192.06 3528.37,2163.36 ccw(c3582.18,2163.36) 3544.13,2125.31 3674.37,1995.07 cw(c3646.3,1967) 3686,1967 3686,1944.44 cw(c3621.89,1944.44) 3667.22,1899.11 3665.56,1897.44 ccw(c3703.11,1859.89) 3650,1859.89 3650,1855.33 ccw(c3667,1855.33) 3667,1838.33 3677,1838.33 cw(c3677,1828.67) 3683.82,1835.51 v2(3690.5,1828.83)
FE2_CSI2_TX2_N: U6.K14 U14.A10 | length 1726.8
  Layer 1 - Top Layer w7: v4(4275.39,1795.67) U6.K14@4288.19,1808.46
  Layer 3 - Signal (Sensitive) w4: v2(3559.5,1984.5) 3565.76,1990.76 cw(c3576,1980.52) 3576,1995 3599.39,1995 ccw(c3599.39,2020.61) 3617.5,2002.5 3709.39,2094.39 cw(c3735,2068.79) 3735,2105 3808.68,2105 cw(c3808.68,2089.68) 3824,2089.68 3824,2080.32 cw(c3808.68,2080.32) 3808.68,2065 3745,2065 ccw(c3745,2035) 3715,2035 3715,1995 ccw(c3745,1995) 3745,1965 3820,1965 cw(c3820,1945) 3840,1945 3840,1911.21 ccw(c3891.21,1911.21) 3854.99,1875.01 3864.39,1865.61 ccw(c3890,1891.21) 3890,1855 cw(c3890,1842.93) 3898.54,1851.46 3955.86,1794.14 cw(c3921.72,1760) 3970,1760 3970,1729.75 ccw(c4029.75,1729.75) 3987.5,1687.5 4022.78,1652.22 ccw(c4100.56,1730) 4100.56,1620 4210,1620 ccw(c4210,1678.28) 4251.21,1637.07 4262.07,1647.93 ccw(c4205.76,1704.24) 4285.39,1704.24 4285.39,1754.58 cw(c4290.23,1754.58) 4286.81,1758 ccw(c4283.48,1761.33) 4288.19,1761.33 4288.19,1777 ccw(c4274.01,1777) 4284.04,1787.03 v4(4275.39,1795.67)
  Layer 8 - Bottom Layer w4: U14.A10@3475.39,2205.83 3475.39,2193.85 3477.19,2192.06 3477.19,2100 ccw(c3530.76,2100) 3492.88,2062.12 3512.5,2042.5 cw(c3496.81,2026.81) 3519,2026.81 3519,2011 ccw(c3536,2011) 3536,1994 3546,1994 cw(c3546,1984.34) 3552.82,1991.17 v2(3559.5,1984.5)
FE2_CSI2_TX2_P: U6.K15 U14.B10 | length 1726.5
  Layer 1 - Top Layer w7: v4(4275.39,1770.08) U6.K15@4288.19,1782.87
  Layer 3 - Signal (Sensitive) w4: v2(3560,2015) 3565.77,2009.23 ccw(c3576,2019.49) 3576,2005 3599.39,2005 ccw(c3599.39,2020.61) 3610.43,2009.57 3617.43,2016.57 ccw(c3611.22,2022.78) 3620,2022.78 3620,2027.17 ccw(c3613.17,2027.17) 3618.01,2031.99 3613.12,2036.88 cw(c3618.24,2042) 3611,2042 3611,2044.76 cw(c3621.24,2044.76) 3614,2052 3618,2056 cw(c3622.83,2051.17) 3622.83,2058 3627.76,2058 cw(c3627.76,2047.76) 3635,2055 3637.17,2052.83 ccw(c3644,2059.66) 3644,2050 3647.22,2050 ccw(c3647.22,2058.78) 3653.43,2052.57 3702.32,2101.46 cw(c3735,2068.79) 3735,2115 3808.68,2115 cw(c3808.68,2089.68) 3834,2089.68 3834,2080.32 cw(c3808.68,2080.32) 3808.68,2055 3745,2055 ccw(c3745,2035) 3725,2035 3725,1995 ccw(c3745,1995) 3745,1975 3820,1975 cw(c3820,1945) 3850,1945 3850,1911.21 ccw(c3891.21,1911.21) 3862.07,1882.07 3871.46,1872.68 ccw(c3890,1891.21) 3890,1865 cw(c3890,1842.93) 3905.61,1858.54 3962.93,1801.21 cw(c3921.72,1760) 3980,1760 3980,1729.75 ccw(c4029.75,1729.75) 3994.57,1694.57 4029.85,1659.29 ccw(c4100.56,1730) 4100.56,1630 4210,1630 ccw(c4210,1678.28) 4244.14,1644.14 4255,1655 ccw(c4205.76,1704.24) 4275.39,1704.24 v4(4275.39,1770.08)
  Layer 8 - Bottom Layer w4: U14.B10@3475.39,2231.42 3488.19,2218.62 3488.19,2100 ccw(c3530.76,2100) 3500.66,2069.9 3520.28,2050.27 cw(c3496.81,2026.81) 3530,2026.81 3530,2011.83 ccw(c3536.83,2011.83) 3536.83,2005 3546,2005 ccw(c3546,2014.66) 3552.82,2007.83 v2(3560,2015)
FE2_CSI2_TX3_N: U6.L14 U14.A9 | length 1726
  Layer 1 - Top Layer w7: v4(4249.8,1795.67) U6.L14@4262.6,1808.46
  Layer 3 - Signal (Sensitive) w4: v2(3489.5,1984.5) 3495.76,1990.76 cw(c3506,1980.52) 3506,1995 3509,1995 ccw(c3509,2016) 3530,2016 3530,2018.27 cw(c3560.73,2018.27) 3539,2040 3614.71,2115.71 cw(c3685.42,2045) 3685.42,2145 4032.2,2145 cw(c4032.2,2107.2) 4070,2107.2 4070,2035 cw(c4031.72,2035) 4058.79,2007.93 4028.54,1977.68 ccw(c4061.21,1945) 4015,1945 4015,1750.47 ccw(c4105.47,1750.47) 4105.47,1660 4199.8,1660 ccw(c4199.8,1720) 4259.8,1720 4259.8,1754.58 cw(c4264.64,1754.58) 4261.22,1758 ccw(c4257.89,1761.33) 4262.6,1761.33 4262.6,1777 ccw(c4248.42,1777) 4258.45,1787.03 v4(4249.8,1795.67)
  Layer 8 - Bottom Layer w4: U14.A9@3449.8,2205.83 3449.8,2193.85 3451.6,2192.06 3451.6,2013 ccw(c3470.6,2013) 3470.6,1994 3476,1994 cw(c3476,1984.34) 3482.82,1991.17 v2(3489.5,1984.5)
FE2_CSI2_TX3_P: U6.L15 U14.B9 | length 1726.4
  Layer 1 - Top Layer w7: v4(4249.8,1770.08) U6.L15@4262.6,1782.87
  Layer 3 - Signal (Sensitive) w4: v2(3490,2015) 3495.77,2009.23 ccw(c3506,2019.49) 3506,2005 3509,2005 ccw(c3509,2016) 3520,2016 3520,2018.27 cw(c3560.73,2018.27) 3531.93,2047.07 ccw(c3526.93,2052.07) 3534,2052.07 3534,2054 ccw(c3521.96,2054) 3530.47,2062.51 3526.13,2066.86 cw(c3531.27,2072) 3524,2072 3524,2072.34 cw(c3537.66,2072.34) 3527.99,2081.99 3530.5,2084.5 cw(c3536.54,2078.46) 3536.54,2087 3543.15,2087 cw(c3543.15,2080.15) 3547.99,2085 ; 3547.99,2084.99 3551.86,2081.13 ccw(c3557,2086.27) 3557,2079 ccw(c3557,2095.56) 3568.71,2083.85 3607.64,2122.78 cw(c3685.42,2045) 3685.42,2155 4032.2,2155 cw(c4032.2,2107.2) 4080,2107.2 4080,2035 cw(c4031.72,2035) 4065.86,2000.86 4035.61,1970.61 ccw(c4061.21,1945) 4025,1945 4025,1750.47 ccw(c4105.47,1750.47) 4105.47,1670 4199.8,1670 ccw(c4199.8,1720) 4249.8,1720 v4(4249.8,1770.08)
  Layer 8 - Bottom Layer w4: U14.B9@3449.8,2231.42 3462.6,2218.62 3462.6,2013 ccw(c3470.6,2013) 3470.6,2005 3476,2005 ccw(c3476,2014.66) 3482.82,2007.83 v2(3490,2015)
FE2_GPIO0: U6.N4 U14.V14 | length 2353.9
  Layer 1 - Top Layer w7: v4(4198.62,2077.17) U6.N4@4211.42,2064.37
  Layer 3 - Signal (Sensitive) w4: v4(4198.62,2077.17) 4198.62,2138.62 4215,2155 4398,2155 4550,2307 v2(4550,2475)
  Layer 8 - Bottom Layer w4: U14.V14@3577.75,2640.87 3590.55,2653.66 3590.55,2678.25
  Layer 8 - Bottom Layer w5.5: 3590.55,2678.25 3587.86,2680.95 3587.61,2680.95 3587.61,2757.61 3610,2780 3610,2920 3700,3010 3730,3010 3905,2835 4460,2835 4590,2705 4590,2515 v2(4550,2475)
FE2_GPIO1: U6.N7 U14.U13 | length 1198.3
  Layer 1 - Top Layer w7: v4(4198.62,2000.39) U6.N7@4211.42,1987.6
  Layer 5 - Signal w5: v5(3564.96,2625.93) 3589.07,2625.93 3605,2610 3625,2610 3665,2650 3740,2650 3780,2690 3835,2690 3870,2655 3870,2585 4215,2240 4215,2016.77 v4(4198.62,2000.39)
  Layer 8 - Bottom Layer w4: U14.U13@3552.17,2615.28 v5(3564.96,2625.93)
FE2_GPIO2: U6.N13 U14.W14 | length 2599.7
  Layer 1 - Top Layer w7: v4(4198.62,1821.26) U6.N13@4211.42,1834.06
  Layer 3 - Signal (Sensitive) w4: v4(4198.62,1821.26) 4262.6,1885.24 4340.24,1885.24 4441.73,1986.73 4441.73,2139.73 4625,2323 v2(4625,2500)
  Layer 8 - Bottom Layer w5: 3576.86,2765.79 3576.86,2667.36 U14.W14@3577.75,2666.46
  Layer 8 - Bottom Layer w5.5: 3576.86,2765.79 3595,2783.93 3595,2930 3700,3035 3745,3035 3925,2855 4465,2855 4625,2695 v2(4625,2500)
FE2_I2C_SCL: R156.2 U14.W12 | length 2619.7
  Layer 1 - Top Layer w5.5: v5(3540,2945) 3540,3025 3575,3060 v2(3740,3060)
  Layer 8 - Bottom Layer w5: v2(3740,3060) 3760,3060 3945,2875 4470,2875 4650,2695 4650,2470 4625,2445 4345,2445 4120,2220 4065,2220 4050,2205 R156.2@4050,2173.62
  Layer 8 - Bottom Layer w5.5: U14.W12@3526.57,2666.46 3526.57,2688.43 3520,2695 3520,2715 3530,2725 3530,2772.5 3550,2792.5 3550,2920 3540,2930 v5(3540,2945)
FE2_I2C_SDA: R41.2 U14.T10 | length 873.8
  Layer 1 - Top Layer w8: v2(4020,2215) 4020,2185 4030,2175 4048.62,2175 R41.2@4050,2173.62
  Layer 5 - Signal w5: v5(3475.39,2610) 3503,2610 3528,2585 3547,2585 3557,2595 3571,2595 3581,2585 3598,2585 3608,2595 3624,2595 3634,2585 3649,2585 3659,2595 3680,2595 3700,2575 3700,2515 3920,2295 3975,2295 4020,2250 v2(4020,2215)
  Layer 8 - Bottom Layer w10: U14.T10@3475.39,2589.69 v5(3475.39,2610)
FE2_MCU_CLK_OUT: U6.N9 U14.J2 | length 1551.8
  Layer 1 - Top Layer w7: v4(4198.62,1923.62) U6.N9@4211.42,1936.42
  Layer 3 - Signal (Sensitive) w4: v7(3165,2385) 3185,2365 3293,2365 3311,2347 3360,2347 3429,2278 3520,2278 3552,2310 3575,2310 3582,2303 3596,2303 3607,2314 3624,2314 3633,2305 3650,2305 3660,2315 3745,2315 3785,2275 3818,2275 3838,2295 3950,2295 3960,2285 3995,2285 4060,2220 4115,2220 4125,2210 4125,1997.24 v4(4198.62,1923.62)
  Layer 8 - Bottom Layer w4: 3232.84,2397.76 3257.87,2397.76 U14.J2@3270.67,2410.55
  Layer 8 - Bottom Layer w5.5: v7(3165,2385) 3187,2407 3210.27,2407 3219.51,2397.76 3232.84,2397.76
FE2_nERROR_OUT: R164.1 R168.2 U6.N8 | length 324.2
  Layer 1 - Top Layer w7: v4(4198.62,1949.21) U6.N8@4211.42,1962.01
  Layer 8 - Bottom Layer w8: R168.2@3938.23,2010.31 3939.01,2010.31 3963.7,2035 3985,2035 4008.16,2011.84 4023.47,2011.84 R164.1@4025,2010.32 4055,2010.32 4072.66,1992.66 4127.34,1992.66 4145,1975 4172.83,1975 v4(4198.62,1949.21)
FE2_nRESET: R187.2 R190.2 TP33.1 U6.P12 | length 341.1
  Layer 1 - Top Layer w7: v4(4173.03,1846.85) U6.P12@4185.83,1859.65
  Layer 5 - Signal w5: TP33.1@3940,1885 TP33.1@3940,1880 3957,1863 3997,1863 4020,1840 v2(4065,1840)
  Layer 8 - Bottom Layer w8: R187.2@3907.99,1880 TP33.1@3940,1880 ; R190.2@4039.68,1840 v2(4065,1840) 4075,1830 4095,1830 4111.85,1846.85 v4(4173.03,1846.85)
FE2_nWARM_RESET: R54.2 R180.1 TP30.1 U6.N12 | length 386.2
  Layer 1 - Top Layer w5: R54.2@3897.99,1925 TP30.1@3940,1925
  Layer 1 - Top Layer w7: v4(4198.62,1846.85) U6.N12@4211.42,1859.65
  Layer 5 - Signal w5: TP30.1@3940,1925 3958,1907 3998,1907 4025,1880 4110,1880 4130.35,1859.65 4185.83,1859.65 v4(4198.62,1846.85)
  Layer 8 - Bottom Layer w5: R180.1@3904.92,1925 TP30.1@3940,1925
FE2_RS232_RX: TP23.1 U6.N5 | length 369.1
  Layer 1 - Top Layer w7: v4(4198.62,2051.57) U6.N5@4211.42,2038.78
  Layer 5 - Signal w5: TP23.1@3885.23,2080 3910,2055.23 3910,2045 3916.22,2038.78 3948.78,2038.78 3960,2050 4138.78,2050 4150,2038.78 4185.83,2038.78 v4(4198.62,2051.57)
FE2_RS232_TX: TP29.1 U6.N6 | length 333.5
  Layer 1 - Top Layer w7: v4(4198.62,2025.98) U6.N6@4211.42,2013.19
  Layer 5 - Signal w5: TP29.1@3940,1975 3940,2005 3970,2035 4125,2035 4146.81,2013.19 4185.83,2013.19 v4(4198.62,2025.98)
FE2_RX1: "E1.D2 - RX1" U6.M2 | length 686.3
  Layer 1 - Top Layer w8.4: 3999.21,2712.01 3999.21,2567.41 ccw(c4099.21,2567.41) 4028.5,2496.7 4207.72,2317.48 cw(c4137.01,2246.77) 4237.01,2246.77 U6.M2@4237.01,2115.55
FE2_RX2: "E1.D2 - RX2" U6.K2 | length 686.8
  Layer 1 - Top Layer w8.4: 4074.02,2712.01 4074.02,2624.43 ccw(c4287.08,2624.43) 4136.42,2473.78 4177.58,2432.61 ccw(c4203.19,2458.22) 4203.19,2422.01 cw(c4203.19,2385.79) 4228.8,2411.4 4263.19,2377.01 cw(c4202.83,2316.65) 4288.17,2318.45 cw(c4202.83,2316.65) 4288.19,2316.65 U6.K2@4288.19,2115.55
FE2_RX3: "E1.D2 - RX3" U6.H2 | length 686.3
  Layer 1 - Top Layer w8.4: 4148.82,2712.01 4148.82,2608.62 ccw(c4299.09,2608.62) 4192.83,2502.36 ccw(c4237.19,2546.78) 4237.19,2484.01 cw(c4237.19,2423.65) 4279.87,2466.33 4290.12,2456.08 cw(c4171.2,2337.17) 4339.37,2337.17 U6.H2@4339.37,2115.55
FE2_RX4: "E1.D2 - RX4" U6.F2 | length 686.3
  Layer 1 - Top Layer w8.4: 4223.62,2712.01 4223.62,2597.18 ccw(c4273.36,2597.18) 4238.19,2562.01 ccw(c4274.4,2598.22) 4274.4,2547.01 4278.19,2547.01 cw(c4278.19,2462.51) 4337.94,2522.26 4346.42,2513.77 cw(c4239.89,2407.24) 4390.55,2407.24 U6.F2@4390.55,2115.55
FE2_SCALED: C127.1 R137.2 R138.1 U14.N2 | length 474.8
  Layer 8 - Bottom Layer w4: 3236.41,2500.12 3257.87,2500.12 U14.N2@3270.67,2512.91
  Layer 8 - Bottom Layer w5.5: R138.1@2925,2616.38 R137.2@2970,2616.38 2970,2612.44 2981.66,2600.78 2981.78,2600.78 2985,2597.56 2985,2520 2996,2509 3014,2509 3034,2489 3051,2489 C127.1@3060,2480 ; C127.1@3057.5,2482.5 3087,2512 3224.52,2512 3236.41,2500.12
FE2_SOP0: R192.2 R197.1 TP37.1 U6.J13 | length 607.4
  Layer 1 - Top Layer w7: v4(4300.98,1821.26) U6.J13@4313.78,1834.06
  Layer 5 - Signal w5: TP37.1@3865,1755 4185.95,1755 4211.2,1780.24 4211.2,1829.2 4216.28,1834.28 4287.97,1834.28 v4(4300.98,1821.26)
  Layer 8 - Bottom Layer w8: TP37.1@3865,1755 R197.1@3906.38,1755 R192.2@3906.38,1800
FE2_SOP1: R178.1 R186.2 U6.P11 | length 206.3
  Layer 1 - Top Layer w7: v4(4173.03,1872.44) U6.P11@4185.83,1885.24
  Layer 8 - Bottom Layer w8: R186.2@4053.62,1885 R178.1@4053.62,1930 4092,1930 4149.56,1872.44 v4(4173.03,1872.44)
FE2_SOP2: R191.2 R196.1 U6.P13 | length 186.3
  Layer 1 - Top Layer w7: v4(4173.03,1821.26) U6.P13@4185.83,1834.06
  Layer 8 - Bottom Layer w8: R196.1@4058.62,1755 R191.2@4058.62,1800 4063.62,1805 4100,1805 4116.26,1821.26 v4(4173.03,1821.26)
FE2_SPI_CLK: R131.1 U6.R9 | length 1338.9
  Layer 1 - Top Layer w7: v4(4147.44,1923.62) U6.R9@4160.24,1936.42
  Layer 3 - Signal (Sensitive) w4: v4(4147.44,1923.62) 4147.44,1872.56 4160.35,1859.65 4214.65,1859.65 4230,1875 4230,2060 4240,2070 4352,2070 4595,2313 4595,2665 4520,2740 v2(4495,2740)
  Layer 8 - Bottom Layer w8: R131.1@4463.62,2755 4465,2755 4480,2740 v2(4495,2740)
FE2_SPI_CS0: R24.1 R53.1 U6.R7 U14.U17 | length 2096.2
  Layer 1 - Top Layer w8: v5(3642.76,2603.51) 3642.76,2631.38 R24.1@3645,2631.38 3673.62,2631.38 3690,2615 3690,2595 3700,2585 3720,2585 3756,2621 3834,2621 3850,2605 3850,2505 3830,2485 3815,2485 3805,2475 3805,2415 3815,2405 3850,2405 3865,2390 3865,2375 3852.5,2362.5 3842.5,2362.5 3830,2350 3830,2335 3850,2315 3885,2315 3895,2305 3895,2225 3915,2205 3915,2155 3895,2135 3875,2135 3830,2090 3830,2050 3850,2030 3850,1990 3835,1975 3835,1920 3785,1870 3785,1725 3810,1700 3890,1700 3910,1720 3910,1740 3920,1750 3945,1750 3955,1740 3955,1715 3970,1700 4005,1700 4025,1720 4025,1880 4049.68,1904.68 R53.1@4049.68,1930 4102.64,1930 U6.R7@4160.24,1987.6
  Layer 8 - Bottom Layer w5.5: v5(3642.76,2603.51) U14.U17@3654.53,2615.28
FE2_SPI_IRQ: R128.2 R159.2 U6.P6 U14.W18 | length 1987.5
  Layer 1 - Top Layer w7: v2@3715.5,2720.82 v2(3714.68,2720) 3714.68,2755.16 3704.84,2765 3675,2765 3665,2755 3665,2735 3690,2710 3690,2660 3713,2637 3843,2637 3875,2605 3875,2575 3885,2565 3920,2565 3930,2555 3930,2535 3920,2525 3900,2525 3880,2505 3880,2475 3855,2450 3855,2435 3865,2425 3880,2425 3890,2415 3890,2375 3910,2355 3960,2355 3970,2345 3970,2330 3960,2320 3930,2320 3920,2310 3920,2290 3930,2280 3950,2280 3965,2295 4015,2295 4045,2265 4065,2265 4075,2255 4075,2225 4065,2215 4055,2215 4030,2240 3960,2240 3950,2230 3950,2210 3960,2200 3990,2200 4000,2190 4000,2175 4020,2155 4020,2140 4010,2130 3990,2130 3980,2140 3980,2160 3975,2165 3955,2165 3945,2155 3945,2135 3955,2125 3955,2114.69 v2(3964.68,2105) ; v4(4173.03,2025.98) U6.P6@4185.83,2013.19
  Layer 8 - Bottom Layer w5.5: U14.W18@3680.12,2666.46 3715,2701.34 R128.2@3715,2771.38
  Layer 8 - Bottom Layer w7: v2(3964.68,2105) 3984.68,2125 4010,2125 4049.68,2085.32 R159.2@4049.68,2085 4105,2085 4164.02,2025.98 v4(4173.03,2025.98)
FE2_SPI_MISO: U6.P5 U14.V18 | length 2095.6
  Layer 1 - Top Layer w7: v4(4173.03,2051.57) U6.P5@4185.83,2038.78
  Layer 3 - Signal (Sensitive) w4: v4(4173.03,2051.57) 4155,2069.61 4155,2115 4210,2170 4210,2245 4225,2260 4240,2260 4255,2245 4255,2180 4265,2170 4395,2170 4520,2295 v2(4520,2500)
  Layer 8 - Bottom Layer w4: U14.V18@3680.12,2640.87 3692.91,2653.66 3716.66,2653.66 3848,2785 4335,2785
  Layer 8 - Bottom Layer w5.5: 4335,2785 4485,2785 4570,2700 4570,2550 v2(4520,2500)
FE2_SPI_MOSI: R139.1 U6.R8 | length 1332.2
  Layer 1 - Top Layer w7: v4(4147.44,1949.21) U6.R8@4160.24,1962.01
  Layer 3 - Signal (Sensitive) w4: v4(4147.44,1949.21) 4165,1931.65 4165,1900 4179.76,1885.24 4211.42,1885.24 4215.59,1889.41 4215.59,2120.59 4225,2130 4245,2130 4255,2120 4255,2095 4265,2085 4280,2085 4290,2095 4290,2110 4300,2120 4310,2120 4330,2100 4362,2100 4575,2313 4575,2645 4555,2665 v2(4495,2665)
  Layer 8 - Bottom Layer w8: R139.1@4463.62,2665 v2(4495,2665)
FE2_SYNC_IN: R176.2 R184.1 U6.N10 | length 1241
  Layer 1 - Top Layer w7: v4(4198.62,1898.03) U6.N10@4211.42,1910.83
  Layer 5 - Signal w5: v2(3605,1841.38) 3605,1680 3625,1660 3775,1660 3815,1700 3815,1895 3870,1950 4075,1950 4126.97,1898.03 v4(4198.62,1898.03)
  Layer 8 - Bottom Layer w7: R176.2@4049.68,1970 4075,1970 4146.97,1898.03 v4(4198.62,1898.03)
  Layer 8 - Bottom Layer w8: R184.1@3580,1841.38 v2(3605,1841.38)
FE2_TX1: "E2.D2 - TX1" U6.B4 | length 1554.6
  Layer 1 - Top Layer w8.4: U6.B4@4492.91,2064.37 4569.37,2064.37 cw(c4569.37,1887.01) 4746.73,1887.01 4746.73,1604.65 cw(c4551.73,1604.65) 4551.73,1409.65 4325.32,1409.65 ccw(c4325.32,1372.75) 4288.43,1372.75 4288.43,1349.56 ccw(c4325.98,1349.56) 4325.98,1312.01 4440.01,1312.01 cw(c4440.01,1258.95) 4493.07,1258.95 4493.07,1212.01
FE2_TX2: "E2.D2 - TX2" U6.B6 | length 1554.3
  Layer 1 - Top Layer w8.4: 4184.53,1212.01 4184.53,1273.46 ccw(c4145.98,1273.46) 4145.98,1312.01 4123.78,1312.01 cw(c4123.78,1359.81) 4075.98,1359.81 4075.98,1403.25 cw(c4133.56,1403.25) 4133.56,1460.83 4551.73,1460.83 ccw(c4551.73,1604.65) 4695.55,1604.65 4695.55,1887.01 ccw(c4569.37,1887.01) 4569.37,2013.19 U6.B6@4492.91,2013.19
FE2_TX3: "E2.D2 - TX3" U6.B8 | length 1554.7
  Layer 1 - Top Layer w8.4: 3875.98,1212.01 3875.98,1411.34 cw(c3976.65,1411.34) 3976.65,1512.01 4551.73,1512.01 ccw(c4551.73,1604.65) 4644.37,1604.65 4644.37,1887.01 ccw(c4569.37,1887.01) 4569.37,1962.01 U6.B8@4492.91,1962.01
FE2_VRF1_FILTERED: C125.1 C131.1 C140.1 C146.1 C184.1 C186.1 C188.1 C190.1 L16.2 U6.G5 U6.H5 U6.J5 U14.N1 | length 1857.9
  Layer 1 - Top Layer w7: v4(4300.98,2051.57) U6.J5@4313.78,2038.78 ; v4(4326.57,2051.57) U6.H5@4339.37,2038.78 ; U6.G5@4364.96,2038.78 v4(4377.76,2051.58)
  Layer 6 - PWR / Signal w20: v2(2230,1515) 2460,1515 2630,1685 2685,1685 2790,1790 2790,2055 2875,2140 2875,2481 2924,2530 v2(3010,2530)
  Layer 8 - Bottom Layer w5.5: C125.1@3045,2520 3050,2525 3232.99,2525 U14.N1@3245.08,2512.91 U14.N1@3243.78,2514.21
  Layer 8 - Bottom Layer w15: v2(3010,2530) 3025,2530 3035.29,2519.71 C125.1@3045,2519.71
FE2_VRF2_FILTERED: C25.1 C133.1 C139.1 C185.1 C187.1 C189.1 C191.1 L17.2 R45.2 U6.C2 U6.D2 U14.M1 | length 1838.7
  Layer 1 - Top Layer w7: U6.D2@4441.73,2115.55 v4(4454.53,2128.35) ; U6.C2@4467.32,2115.55 v4(4480.12,2128.35)
  Layer 1 - Top Layer w10: v2(2865,2530) 2889,2506 3036.5,2506 3060,2482.5 C25.1@3060,2480 ; C25.1@3060,2475 C25.1@3060,2480 ; v7(3090,2480) C25.1@3060,2480
  Layer 6 - PWR / Signal w20: v2(2230,1595) 2265,1630 2525,1630 2615,1720 2670,1720 2754.36,1804.36 2754.36,2069.36 2840,2155 2840,2505 v2(2865,2530)
  Layer 8 - Bottom Layer w5.5: v7(3090,2480) 3109,2499 3221.96,2499 3233.63,2487.32 U14.M1@3245.08,2487.32
  other v2: 4818.39,2070 4848.39,2070 4818.39,2100 4848.39,2100
FE_SYNC_BUFFER_ENABLE: R199.2 U14.A18 | length 748.9
  Layer 1 - Top Layer w5.5: v2(3665,1725) 3665,1745 3736.5,1816.5 3736.5,1918.5 3805,1987 3805,2104 3849,2148 3849,2166 v7(3830,2185)
  Layer 8 - Bottom Layer w5.5: U14.A18@3680.12,2205.83 3718.95,2167 3812,2167 v7(3830,2185)
  Layer 8 - Bottom Layer w8: R199.2@3633.62,1725 v2(3665,1725)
